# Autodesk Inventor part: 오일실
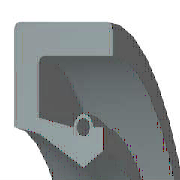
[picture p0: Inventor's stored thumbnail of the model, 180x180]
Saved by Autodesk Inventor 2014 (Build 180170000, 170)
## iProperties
Created: 2009-02
Part Number: 오일실
Material: 고무
Description: 오일-실
Document SubType Name: Modeling
Standard: KS B 2804
Designer: KYOUNG IL JANG
Standards Organization: KS
Language: ko-KR
Size Designation: S - 18 30 8
Categories: <MemberInstance><Categories><Category DisplayName="샤프트 부품" InternalName="7f7aeb1f-a693-4053-b835-cee3144e0d98" Mnemonic="SHFT"><Category DisplayName="실링" Intern
Density: 0.93 g/cm^3
Appearance: 고무 - 검은색 - 버전 1.1
Company: 한국ATC센터
IsCustomPart: 1
Author: KYOUNG IL JANG
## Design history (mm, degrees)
revolve "본체" stored, may be unused: angle "d17" = 90 deg
revolve "스프링1" stored, may be unused: angle "d18" = 90 deg
body "Solid1"
sketch "스케치1"
  geometry: L1 (0, 15)-(8, 15); L2 (8, 15)-(8, 13.75); L3 (8, 13.75)-(1.75, 13.75); L4 (0, 15)-(0, 11.1); L5 (0, 11.1)-(1.75, 10.75); L6 (1.75, 10.75)-(4.9, 9); L7 (4.9, 9)-(0, 9); L8 (6.3, 9.875)-(6.3, 11.1); L9 (0, 0)-(9.586, 0) reference; L10 (4.9, 9)-(6.3, 9.875); L11 (0, 18)-(0, -3) reference; L12 (-1.917, 0)-(11.503, 0) reference; L13 (4.2, 11.1)-(1.75, 11.59); L14 (1.75, 11.59)-(1.75, 13.75); L15 (6.3, 11.1)-(5.6, 11.1); C1 r 0.455 at (4.9, 11.1); A1 r 0.7 centre (4.9, 11.1) between (5.6, 11.1) and (4.2, 11.1)
  constraints: 26 end point, 5 horizontal alignment, 4 perpendicular, 2 centre point, 2 collinear, 2 horizontal, 2 parallel, 2 point on circle, 2 point on line, 2 vertical alignment, 1 coincident
  dimensions: "d0" = 30 diameter of L1 L9 (= SD2); "d1" = 19.75 diameter of L8.start L9 (= ABDM); "d2" = 1.25 distance of L1.end L2.end (computed from SD); "d3" = 0.91 diameter of C1 (= SPDI); "d4" = 1.4 diameter of A1 (= SPDA); "d5" = 18 diameter of L6.end L9 (= NND); "d6" = 21.5 diameter of L5.end L9 (= TKDM); "d7" = 22.2 diameter of L4.end L9 (= HLDM); "d8" = 4.9 distance from line of C1.centre L4 (= SPDST); "d9" = 6.3 distance between parallel lines of L8 L4 (= SDI); "d10" = 8 distance between parallel lines of L2 L4 (= SWDT); "d12" = 1.75 distance between parallel lines of L14 L4 (= SD)
fillet "모깎기1" dims "d11" = 0.3 (= RR)
other parameters: "SD2" = 30 [user parameter; used in 1 equation term], "SWDT" = 8 [user parameter; used in 1 equation term], "RR" = 0.3 [user parameter; used in 1 equation term], "SD" = 1.75 [user parameter; used in 2 equation terms], "NND" = 18 [user parameter; used in 1 equation term], "SPDA" = 1.4 [user parameter; used in 1 equation term], "SPDI" = 0.91 [user parameter; used in 1 equation term], "TKDM" = 21.5 [user parameter; used in 1 equation term], "HLDM" = 22.2 [user parameter; used in 1 equation term], "ABDM" = 19.75 [user parameter; used in 1 equation term], "SDI" = 6.3 [user parameter; used in 1 equation term], "SPDST" = 4.9 [user parameter; used in 1 equation term], "d13" = 0, "d14" = 0, "d15" = 0, "LAB" = 0.35 [user parameter]
